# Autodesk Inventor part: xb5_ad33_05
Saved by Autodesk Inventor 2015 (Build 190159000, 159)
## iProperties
Created: 2018-05
Part Number: xb5_ad33_05
Checked By: TraceParts S.A.
Material: Generic
Catalog Web Link: www.traceparts.com
Document SubType Name: Modeling
Designer: TraceParts
Density: 1 g/cm^3
Appearance: Default
Company: TraceParts S.A.
Author: TraceParts
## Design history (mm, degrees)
feature "xb5_ad33_05.ipt"
body "Solid1"
